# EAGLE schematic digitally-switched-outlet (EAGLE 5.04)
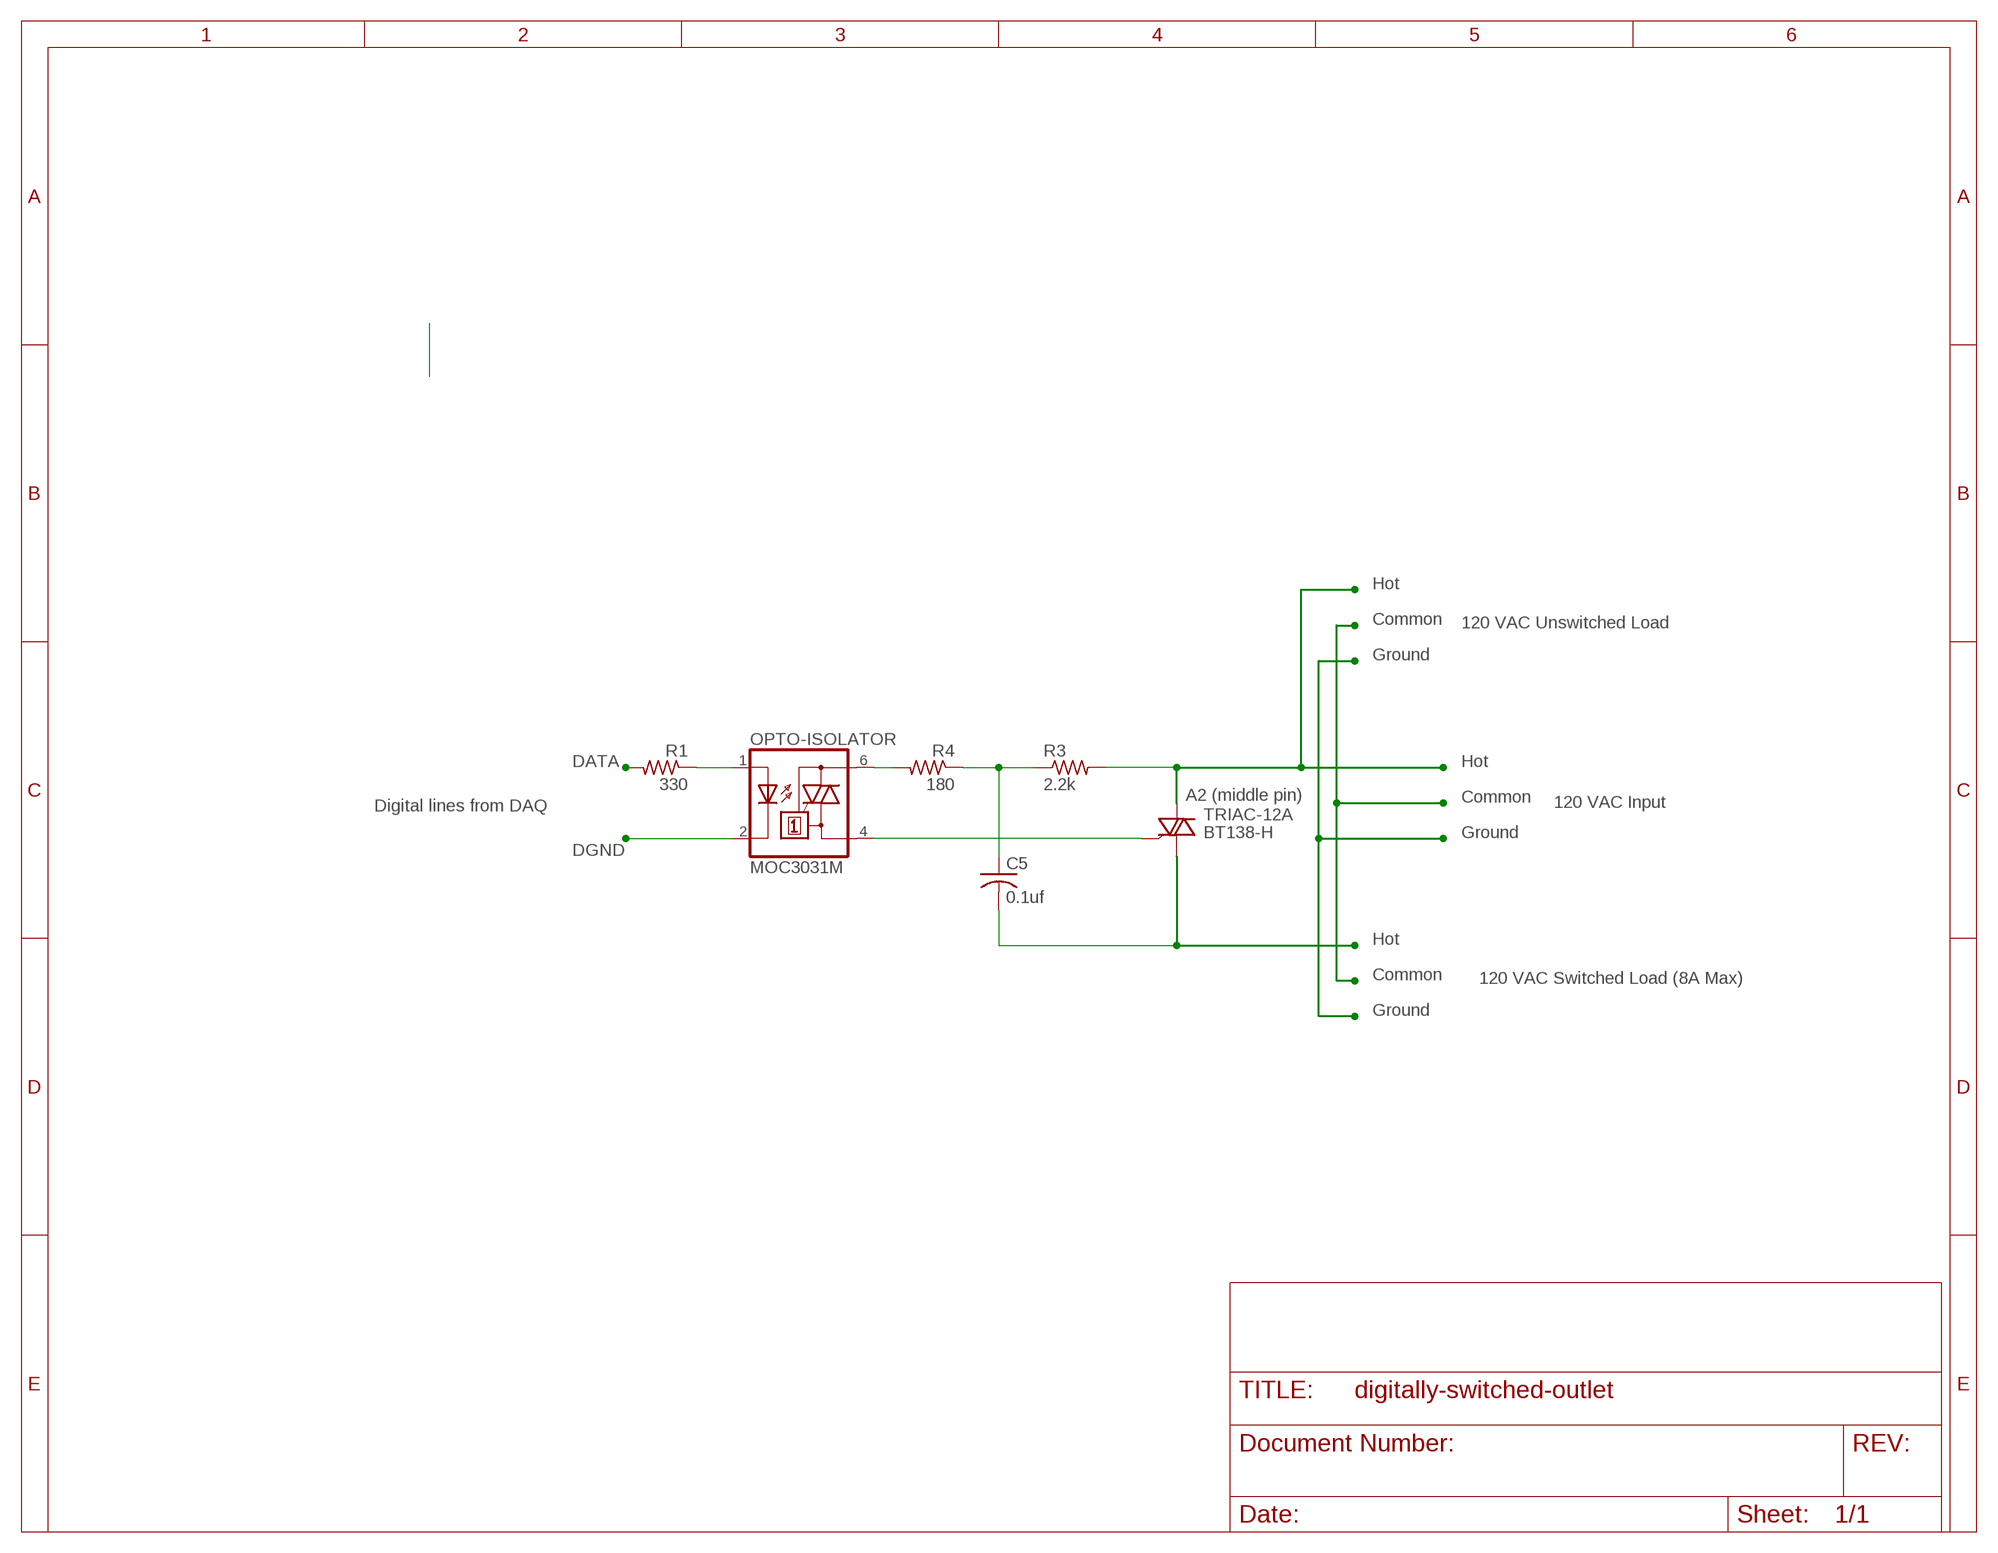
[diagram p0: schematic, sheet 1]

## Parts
C5  0.1uf  C-US050-035X075  [C050-035X075]
OPTO-ISOLATOR  MOC3031M  [DIL06]
R1  330  R-US_0204/5  [0204/5]
R3  2.2k  R-US_0204/5  [0204/5]
R4  180  R-US_0204/5  [0204/5]
TRIAC-12A  BT138-H  [TO220BH]

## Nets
N$1: OPTO-ISOLATOR.2(C)
N$3: R1.2
N$5: OPTO-ISOLATOR.4(A1) TRIAC-12A.G
N$13: OPTO-ISOLATOR.1(A) R1.1
N$14: OPTO-ISOLATOR.6(A2) R4.2
N$15: C5.1 R3.1 R4.1
N$16: C5.2 R3.2 TRIAC-12A.T1(A1) TRIAC-12A.T2(A2)

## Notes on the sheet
- Hot
- Common | 120 VAC Unswitched Load
- Ground
- DATA | Hot
- Digital lines from DAQ | A2 (middle pin) | Common
- 120 VAC Input
- Ground
- DGND
- Hot
- Common | 120 VAC Switched Load (8A Max)
- Ground

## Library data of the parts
C5 = rcl:C-US: CAPACITOR, American symbol
OPTO-ISOLATOR = optocoupler:MOC30*: 6-Pin DIP Zero-Cross Optoisolators Triac Driver Output (250/400 Volt Peak) Source: http://www.fairchildsemi.com/ds/MO/MOC3043-M.pdf
R1 R3 R4 = resistor:R-US_: RESISTOR, American symbol
TRIAC-12A = triac:BT138: TRIAC Source: http://www.semiconductors.philips.com BT138_SERIES_2.pdf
